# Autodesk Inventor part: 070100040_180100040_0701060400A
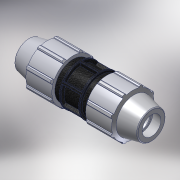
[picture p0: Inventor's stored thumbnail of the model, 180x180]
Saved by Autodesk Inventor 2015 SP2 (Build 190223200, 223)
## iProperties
Created: 2017-02
Part Number: 070100040_180100040_0701060400A
Material: PVC-Piping
Description: PLASSON COUPLER 40-40
Document SubType Name: Modeling
Designer: KIM
Mass: 92.6774 g
Surface Area: 199.44 cm^2
Volume: 66.1981 cm^3
Density: 1.4 g/cm^3
Appearance: PTFE
Author: KIM
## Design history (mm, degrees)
derived "07010.ipt"
feature "Solid1::07010.ipt"
tag "TaggingFeature1"
body "Solid1"
other parameters: "d1" = 177, "d4" = 14.75, "d5" = 25.28571, "d7" = 82, "d8" = 61.5, "d9" = 25.28571, "d11" = 2.52857, "d12" = 65.6, "d13" = 120 deg, "d15" = 10 deg, "d16" = 73.8, "d18" = 2, "d19" = 35 deg, "d20" = 17.5 deg, "d21" = 76.26, "d23" = 0, "d25" = 360 deg, "d27" = 1.64, "d33" = 0.8, "d34" = 4.1, "d36" = 0, "d37" = 0.8, "d38" = 0.8, "d40" = 360 deg, "d42" = 38.94, "d43" = 2.46, "d46" = 1.2, "d49" = 87, "d50" = 32, "E_" = 82, "H_" = 177, "l_" = 87
